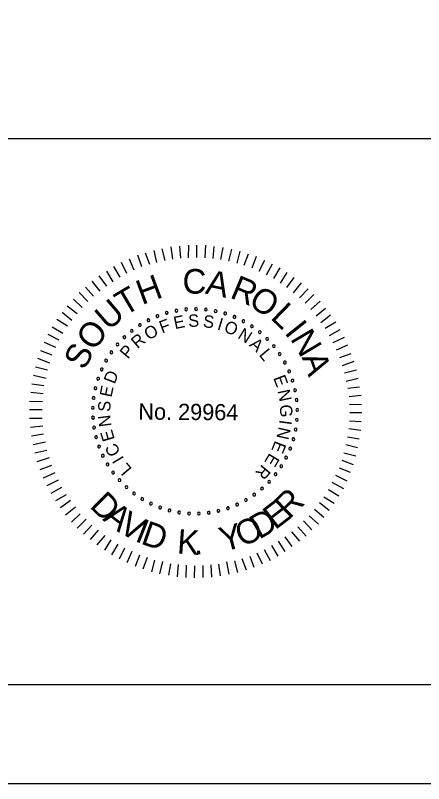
# Model space of a CAD drawing. Extents: x -133.1 to -97, y -1.7 to 20.6.
# Drawn here: x -109.74 to -107.68, y -1.691 to 2.18 of the extents above; entities that cross this region are included whole.
import ezdxf

# ---------------------------------------------------------------- set-up
doc = ezdxf.new("R2010")
doc.units = 0
for name, color, linetype in [('BR_BORDER LINES', 7, 'Continuous'), ('BR_TEXT', 7, 'Continuous'), ('Level 31', 7, 'Continuous')]:
    doc.layers.add(name, color=color, linetype=linetype)

msp = doc.modelspace()

# ---------------------------------------------------------------- linework, layer by layer
at = {"layer": 'BR_BORDER LINES'}
for p, q in [((-110.5071, 1.5591), (-105.1419, 1.5591)), ((-131.3076, -1.191), (-97.6416, -1.191))]:
    msp.add_line(p, q, dxfattribs=at)
at = {"layer": 'BR_TEXT'}
for p, q in [((-108.9454, 0.9521), (-108.9543, 1.0131)), ((-108.9059, 0.9561), (-108.9097, 1.017)), ((-108.8664, 0.9584), (-108.8658, 1.0227)), ((-108.8243, 0.9606), (-108.8238, 1.0224)), ((-108.7823, 0.9577), (-108.78, 1.022)), ((-108.742, 0.9548), (-108.7372, 1.0156)), ((-108.7034, 0.9501), (-108.6926, 1.011)), ((-109.1019, 0.9122), (-109.1229, 0.9708)), ((-109.0623, 0.9248), (-109.0842, 0.9824)), ((-109.0262, 0.9348), (-109.0394, 0.9958)), ((-108.9849, 0.9447), (-108.999, 1.0041)), ((-108.6631, 0.9421), (-108.6489, 1.0012)), ((-108.622, 0.9314), (-108.606, 0.9922)), ((-108.5852, 0.9208), (-108.5633, 0.9781)), ((-109.1777, 0.8785), (-109.2039, 0.9345)), ((-109.1406, 0.8954), (-109.1642, 0.9514)), ((-108.5458, 0.9076), (-108.5239, 0.9658)), ((-108.5099, 0.8902), (-108.482, 0.9457)), ((-109.2475, 0.8371), (-109.278, 0.8914)), ((-109.2122, 0.8608), (-109.2426, 0.9151)), ((-108.474, 0.8727), (-108.4427, 0.9282)), ((-108.4364, 0.8544), (-108.4042, 0.9082)), ((-109.2786, 0.8159), (-109.3177, 0.8668)), ((-108.4031, 0.8301), (-108.3692, 0.8839)), ((-108.3699, 0.8083), (-108.3334, 0.8587)), ((-109.3123, 0.7904), (-109.3522, 0.8405)), ((-108.3375, 0.7824), (-108.2968, 0.8318)), ((-109.3745, 0.7386), (-109.4188, 0.7827)), ((-109.3451, 0.7658), (-109.3868, 0.8107)), ((-108.3059, 0.7572), (-108.2627, 0.8014)), ((-109.4039, 0.7079), (-109.4474, 0.7503)), ((-108.2779, 0.7295), (-108.2346, 0.7729)), ((-108.2498, 0.6984), (-108.2022, 0.74)), ((-109.4291, 0.6763), (-109.4786, 0.7154)), ((-108.2226, 0.6664), (-108.1759, 0.7046)), ((-109.4551, 0.6431), (-109.5046, 0.683)), ((-108.1988, 0.6327), (-108.1496, 0.6718)), ((-109.4768, 0.6141), (-109.5306, 0.6472)), ((-108.1768, 0.6034), (-108.1242, 0.6355)), ((-109.5012, 0.5774), (-109.5549, 0.6096)), ((-108.1548, 0.5663), (-108.1013, 0.5976)), ((-109.5186, 0.5432), (-109.575, 0.5711)), ((-108.137, 0.5318), (-108.0793, 0.5588)), ((-109.5361, 0.5065), (-109.5933, 0.5318)), ((-108.1193, 0.4948), (-108.0624, 0.5192)), ((-109.5536, 0.468), (-109.6117, 0.4899)), ((-108.1025, 0.456), (-108.0456, 0.477)), ((-109.5659, 0.4278), (-109.6275, 0.4506)), ((-108.0891, 0.4156), (-108.0314, 0.4374)), ((-109.5782, 0.3918), (-109.639, 0.4069)), ((-108.079, 0.3794), (-108.0189, 0.3935)), ((-109.5854, 0.3498), (-109.6479, 0.3658)), ((-108.0708, 0.3373), (-108.0106, 0.3522)), ((-109.596, 0.3138), (-109.6569, 0.3221)), ((-109.6006, 0.2727), (-109.6624, 0.2801)), ((-108.0625, 0.3012), (-108.0033, 0.3084)), ((-109.6035, 0.2333), (-109.6679, 0.2338)), ((-108.056, 0.26), (-107.995, 0.2663)), ((-108.0546, 0.2205), (-107.9945, 0.22)), ((-109.6056, 0.1921), (-109.6682, 0.1926)), ((-108.0524, 0.1793), (-107.9915, 0.1788)), ((-109.6042, 0.1492), (-109.6686, 0.148)), ((-108.0553, 0.1364), (-107.9952, 0.1342)), ((-109.602, 0.1105), (-109.6638, 0.1033)), ((-108.0574, 0.0978), (-107.9965, 0.0896)), ((-109.598, 0.0693), (-109.659, 0.0604)), ((-108.0645, 0.0566), (-108.0054, 0.0467)), ((-109.5881, 0.0297), (-109.6508, 0.0165)), ((-108.0735, 0.0172), (-108.0135, 0.003)), ((-109.5815, -0.0124), (-109.6426, -0.0265)), ((-108.0824, -0.0248), (-108.0224, -0.0398)), ((-109.5698, -0.0493), (-109.6318, -0.0703)), ((-108.093, -0.0615), (-108.0357, -0.0835)), ((-109.5582, -0.0881), (-109.6167, -0.1091)), ((-108.107, -0.1001), (-108.0506, -0.122)), ((-109.5413, -0.1251), (-109.599, -0.1521)), ((-108.1245, -0.1368), (-108.0681, -0.1647)), ((-109.5244, -0.1613), (-109.5813, -0.1909)), ((-108.1428, -0.1727), (-108.0856, -0.2032)), ((-109.5076, -0.1984), (-109.5619, -0.2297)), ((-108.1612, -0.2095), (-108.1082, -0.2417)), ((-109.4838, -0.2355), (-109.5382, -0.2668)), ((-109.4626, -0.2648), (-109.5127, -0.3013)), ((-108.1838, -0.2462), (-108.1317, -0.2784)), ((-109.4372, -0.2985), (-109.4873, -0.3376)), ((-108.2306, -0.3084), (-108.1846, -0.3483)), ((-108.2063, -0.2752), (-108.1577, -0.3125)), ((-109.4125, -0.3321), (-109.4567, -0.373)), ((-108.2583, -0.3417), (-108.2115, -0.3833)), ((-109.3836, -0.3582), (-109.4286, -0.4032)), ((-108.2869, -0.3672), (-108.2444, -0.413)), ((-109.3547, -0.3884), (-109.3971, -0.4344)), ((-109.3222, -0.4144), (-109.363, -0.4613)), ((-108.3474, -0.4225), (-108.3075, -0.47)), ((-108.3155, -0.397), (-108.273, -0.4437)), ((-109.289, -0.4404), (-109.3289, -0.4882)), ((-109.2583, -0.4622), (-109.2896, -0.5142)), ((-108.3802, -0.448), (-108.3446, -0.4963)), ((-109.2233, -0.4847), (-109.2546, -0.5386)), ((-108.4475, -0.4911), (-108.4162, -0.5455)), ((-108.4139, -0.4691), (-108.3808, -0.5217)), ((-109.1891, -0.5048), (-109.2162, -0.5603)), ((-109.1523, -0.5222), (-109.1769, -0.5778)), ((-109.1139, -0.5397), (-109.1358, -0.5962)), ((-108.5216, -0.5274), (-108.4947, -0.5835)), ((-108.4855, -0.5106), (-108.455, -0.5666)), ((-109.0745, -0.552), (-109.0973, -0.6102)), ((-109.0386, -0.5644), (-109.0528, -0.6235)), ((-108.9974, -0.5716), (-109.0126, -0.6333)), ((-108.6756, -0.5742), (-108.6624, -0.6361)), ((-108.6344, -0.5677), (-108.6194, -0.627)), ((-108.5974, -0.556), (-108.5764, -0.6145)), ((-108.5578, -0.5443), (-108.5368, -0.6011)), ((-108.9581, -0.5831), (-108.968, -0.6413)), ((-108.9186, -0.5877), (-108.9234, -0.6494)), ((-108.8792, -0.5906), (-108.8797, -0.6524)), ((-108.8372, -0.5935), (-108.8377, -0.6544)), ((-108.7951, -0.5913), (-108.7939, -0.6531)), ((-108.7547, -0.589), (-108.7509, -0.6509)), ((-108.7161, -0.5851), (-108.7062, -0.6435))]:
    msp.add_line(p, q, dxfattribs=at)
for centre, start, end in [((-108.9278, 0.692), 10.6038, 190.6038), ((-108.8784, 0.6987), 5.0653, 185.0653), ((-108.8784, 0.6987), 185.0653, 5.0653), ((-108.8286, 0.7006), 359.5268, 179.5268), ((-108.8286, 0.7006), 179.5268, 359.5268), ((-108.7789, 0.6977), 173.9884, 353.9884), ((-108.7789, 0.6977), 353.9884, 173.9884), ((-108.7296, 0.69), 348.4499, 168.4499), ((-109.0235, 0.6646), 21.6807, 201.6807), ((-109.0235, 0.6646), 201.6807, 21.6807), ((-108.9763, 0.6806), 16.1422, 196.1422), ((-108.9763, 0.6806), 196.1422, 16.1422), ((-108.9278, 0.692), 190.6038, 10.6038), ((-108.7296, 0.69), 168.4499, 348.4499), ((-108.6814, 0.6776), 162.9114, 342.9114), ((-108.6814, 0.6776), 342.9114, 162.9114), ((-108.6345, 0.6606), 157.373, 337.373), ((-108.6345, 0.6606), 337.373, 157.373), ((-109.1121, 0.6192), 32.7576, 212.7576), ((-109.1121, 0.6192), 212.7576, 32.7576), ((-109.0689, 0.644), 27.2191, 207.2191), ((-109.0689, 0.644), 207.2191, 27.2191), ((-108.5896, 0.6391), 151.8345, 331.8345), ((-108.5896, 0.6391), 331.8345, 151.8345), ((-108.5469, 0.6134), 326.2961, 146.2961), ((-109.1527, 0.5903), 38.2961, 218.2961), ((-109.1527, 0.5903), 218.2961, 38.2961), ((-108.5469, 0.6134), 146.2961, 326.2961), ((-108.5069, 0.5837), 140.7576, 320.7576), ((-108.5069, 0.5837), 320.7576, 140.7576), ((-109.1903, 0.5577), 43.8345, 223.8345), ((-109.1903, 0.5577), 223.8345, 43.8345), ((-108.4699, 0.5503), 135.2191, 315.2191), ((-108.4699, 0.5503), 315.2191, 135.2191), ((-109.2246, 0.5215), 49.373, 229.373), ((-109.2246, 0.5215), 229.373, 49.373), ((-108.4363, 0.5134), 129.6807, 309.6807), ((-108.4363, 0.5134), 309.6807, 129.6807), ((-109.2553, 0.4822), 54.9114, 234.9114), ((-109.2553, 0.4822), 234.9114, 54.9114), ((-108.4065, 0.4735), 124.1422, 304.1422), ((-108.4065, 0.4735), 304.1422, 124.1422), ((-109.282, 0.4402), 60.4499, 240.4499), ((-109.282, 0.4402), 240.4499, 60.4499), ((-108.3806, 0.4309), 118.6038, 298.6038), ((-108.3806, 0.4309), 298.6038, 118.6038), ((-109.3045, 0.3957), 65.9884, 245.9884), ((-109.3045, 0.3957), 245.9884, 65.9884), ((-108.359, 0.3861), 113.0653, 293.0653), ((-108.359, 0.3861), 293.0653, 113.0653), ((-109.3227, 0.3493), 71.5268, 251.5268), ((-109.3227, 0.3493), 251.5268, 71.5268), ((-108.3418, 0.3393), 107.5268, 287.5268), ((-108.3418, 0.3393), 287.5268, 107.5268), ((-109.3363, 0.3014), 77.0653, 257.0653), ((-109.3363, 0.3014), 257.0653, 77.0653), ((-108.3292, 0.2911), 101.9884, 281.9884), ((-108.3292, 0.2911), 281.9884, 101.9884), ((-109.3452, 0.2524), 82.6038, 262.6038), ((-109.3452, 0.2524), 262.6038, 82.6038), ((-108.3213, 0.2419), 96.4499, 276.4499), ((-108.3213, 0.2419), 276.4499, 96.4499), ((-109.3493, 0.2027), 88.1422, 268.1422), ((-109.3493, 0.2027), 268.1422, 88.1422), ((-108.3182, 0.1921), 90.9114, 270.9114), ((-108.3182, 0.1921), 270.9114, 90.9114), ((-109.3486, 0.1529), 93.6807, 273.6807), ((-109.3486, 0.1529), 273.6807, 93.6807), ((-108.3199, 0.1423), 85.373, 265.373), ((-108.3199, 0.1423), 265.373, 85.373), ((-109.3431, 0.1033), 99.2191, 279.2191), ((-109.3431, 0.1033), 279.2191, 99.2191), ((-108.3265, 0.0929), 79.8345, 259.8345), ((-108.3265, 0.0929), 259.8345, 79.8345), ((-109.3328, 0.0546), 104.7576, 284.7576), ((-109.3328, 0.0546), 284.7576, 104.7576), ((-108.3377, 0.0444), 74.2961, 254.2961), ((-108.3377, 0.0444), 254.2961, 74.2961), ((-109.3179, 0.007), 110.2961, 290.2961), ((-109.3179, 0.007), 290.2961, 110.2961), ((-108.3536, -0.0028), 68.7576, 248.7576), ((-108.3536, -0.0028), 248.7576, 68.7576), ((-109.2985, -0.0389), 115.8345, 295.8345), ((-109.2985, -0.0389), 295.8345, 115.8345), ((-109.2747, -0.0826), 121.373, 301.373), ((-109.2747, -0.0826), 301.373, 121.373), ((-108.374, -0.0483), 63.2191, 243.2191), ((-108.374, -0.0483), 243.2191, 63.2191), ((-108.3986, -0.0916), 57.6807, 237.6807), ((-108.3986, -0.0916), 237.6807, 57.6807), ((-109.2468, -0.1239), 126.9114, 306.9114), ((-109.2468, -0.1239), 306.9114, 126.9114), ((-108.4273, -0.1323), 52.1422, 232.1422), ((-108.4273, -0.1323), 232.1422, 52.1422), ((-109.2151, -0.1624), 132.4499, 312.4499), ((-109.2151, -0.1624), 312.4499, 132.4499), ((-109.1798, -0.1975), 137.9884, 317.9884), ((-109.1798, -0.1975), 317.9884, 137.9884), ((-108.4599, -0.1701), 46.6038, 226.6038), ((-108.4599, -0.1701), 226.6038, 46.6038), ((-109.1413, -0.2291), 143.5268, 323.5268), ((-109.1413, -0.2291), 323.5268, 143.5268), ((-108.5351, -0.2353), 35.5268, 215.5268), ((-108.5351, -0.2353), 215.5268, 35.5268), ((-108.4959, -0.2045), 41.0653, 221.0653), ((-108.4959, -0.2045), 221.0653, 41.0653), ((-109.0999, -0.2569), 149.0653, 329.0653), ((-109.0999, -0.2569), 329.0653, 149.0653), ((-108.577, -0.2622), 29.9884, 209.9884), ((-108.577, -0.2622), 209.9884, 29.9884), ((-109.056, -0.2805), 154.6038, 334.6038), ((-109.056, -0.2805), 334.6038, 154.6038), ((-109.01, -0.2997), 160.1422, 340.1422), ((-109.01, -0.2997), 340.1422, 160.1422), ((-108.9624, -0.3145), 345.6807, 165.6807), ((-108.6677, -0.3032), 18.9114, 198.9114), ((-108.6677, -0.3032), 198.9114, 18.9114), ((-108.6214, -0.2849), 24.4499, 204.4499), ((-108.6214, -0.2849), 204.4499, 24.4499), ((-108.9624, -0.3145), 165.6807, 345.6807), ((-108.9136, -0.3245), 171.2191, 351.2191), ((-108.9136, -0.3245), 351.2191, 171.2191), ((-108.8641, -0.3299), 356.7576, 176.7576), ((-108.8641, -0.3299), 176.7576, 356.7576), ((-108.8142, -0.3304), 2.2961, 182.2961), ((-108.8142, -0.3304), 182.2961, 2.2961), ((-108.7646, -0.3261), 7.8345, 187.8345), ((-108.7646, -0.3261), 187.8345, 7.8345), ((-108.7156, -0.317), 13.373, 193.373), ((-108.7156, -0.317), 193.373, 13.373)]:
    msp.add_arc(centre, 0.00701, start, end, dxfattribs=at)
at = {"layer": 'Level 31'}
msp.add_lwpolyline([(-133.1409, -1.691), (-97.141, -1.691), (-97.141, 20.309), (-133.1409, 20.309)], close=True, dxfattribs=at)

# ---------------------------------------------------------------- texts
at = {"layer": 'BR_TEXT'}
for s, height, rotation, p in [('C', 0.1241, 359.5482, (-108.8971, 0.7782)), ('A', 0.1241, 348.1981, (-108.7857, 0.779)), ('H', 0.1241, 20.3637, (-109.1015, 0.7199)), ('R', 0.1241, 337.4344, (-108.6624, 0.7591)), ('T', 0.1241, 30.4992, (-109.1894, 0.6624)), ('O', 0.1239, 326.5869, (-108.5702, 0.7224)), ('U', 0.1241, 40.8022, (-109.2706, 0.5876)), ('L', 0.1241, 315.9488, (-108.4576, 0.6546)), ('E', 0.0622, 11.4103, (-108.9351, 0.5987)), ('S', 0.0622, 2.208, (-108.8672, 0.6097)), ('S', 0.0622, 352.6608, (-108.796, 0.6095)), ('O', 0.1241, 52.0267, (-109.3451, 0.4837)), ('F', 0.0622, 20.6127, (-109.0002, 0.577)), ('I', 0.0622, 343.1136, (-108.7257, 0.5975)), ('O', 0.0622, 338.4392, (-108.6923, 0.5873)), ('I', 0.1241, 308.6613, (-108.3862, 0.5803)), ('O', 0.0622, 30.8477, (-109.0676, 0.541)), ('N', 0.0622, 328.2042, (-108.6227, 0.5559)), ('N', 0.1241, 300.7037, (-108.3556, 0.5509)), ('R', 0.0622, 40.3949, (-109.1237, 0.4971)), ('A', 0.0622, 318.657, (-108.5637, 0.5159)), ('S', 0.1239, 63.2511, (-109.3905, 0.3881)), ('P', 0.0622, 49.9421, (-109.1718, 0.4445)), ('L', 0.0622, 309.4546, (-108.5139, 0.4686)), ('A', 0.1241, 289.4792, (-108.2964, 0.4579)), ('D', 0.0622, 69.0364, (-109.2388, 0.3192)), ('E', 0.0622, 291.049, (-108.44, 0.3533)), ('E', 0.0622, 78.2388, (-109.2553, 0.2526)), ('N', 0.0622, 281.8466, (-108.4179, 0.2882)), ('S', 0.0622, 87.786, (-109.2611, 0.1815)), ('No. 29964', 0.08175, 359.5268, (-109.1199, 0.1431)), ('G', 0.0622, 272.2995, (-108.4061, 0.2179)), ('N', 0.0622, 97.3332, (-109.2549, 0.1105)), ('I', 0.0622, 262.4084, (-108.4065, 0.1441)), ('E', 0.0622, 106.5355, (-109.2379, 0.044)), ('N', 0.0622, 257.7339, (-108.411, 0.1095)), ('C', 0.0622, 116.4266, (-109.208, -0.0235)), ('E', 0.0622, 248.1867, (-108.4291, 0.0406)), ('E', 0.0622, 238.9844, (-108.457, -0.0222)), ('I', 0.0622, 121.1011, (-109.1899, -0.0534)), ('L', 0.0622, 129.9595, (-109.1493, -0.1056)), ('R', 0.0622, 229.782, (-108.4947, -0.0797)), ('D', 0.1236, 315.4053, (-109.3698, -0.2962)), ('R', 0.1236, 44.5947, (-108.3589, -0.3617)), ('E', 0.1236, 37.5339, (-108.4295, -0.4156)), ('A', 0.1236, 322.8377, (-109.3032, -0.3618)), ('V', 0.1236, 330.5179, (-109.226, -0.42)), ('D', 0.1236, 30.1015, (-108.5104, -0.4626)), ('I', 0.1236, 338.1981, (-109.1418, -0.4674)), ('D', 0.1236, 340.7995, (-109.1119, -0.4808)), ('Y', 0.1236, 14.8649, (-108.6915, -0.5241)), ('O', 0.1236, 22.4212, (-108.5997, -0.4996)), ('K', 0.1236, 356.098, (-108.9267, -0.5314)), ('.', 0.1236, 3.1588, (-108.838, -0.5377))]:
    msp.add_text(s, height=height, rotation=rotation, dxfattribs=at).set_placement(p)

doc.saveas('drawing.dxf')
